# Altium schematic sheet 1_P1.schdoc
size 518 x 218 mm; Symbol: Drawing-Symbol_A4; Device: Drawing-Symbol_A4; @Project Name: LED tower pcb; @Page Count: 1; @Update Date: 2025-07-06; @Create Date: 2025-07-06; @Schematic Name: Schematic1; @Page No: 1; @Page Name: P1; Company: EasyEDA.com; Version: V1.0; Page Size: A4; @Create Time: 21:22:16; @Update Time: 17:22:16; Width: 2000; Height: 825; Region Start: 1; X Region Count: 6; Y Region Count: 4; Blade Width: 10; Title Block Position: 3; @Board Name: Board1
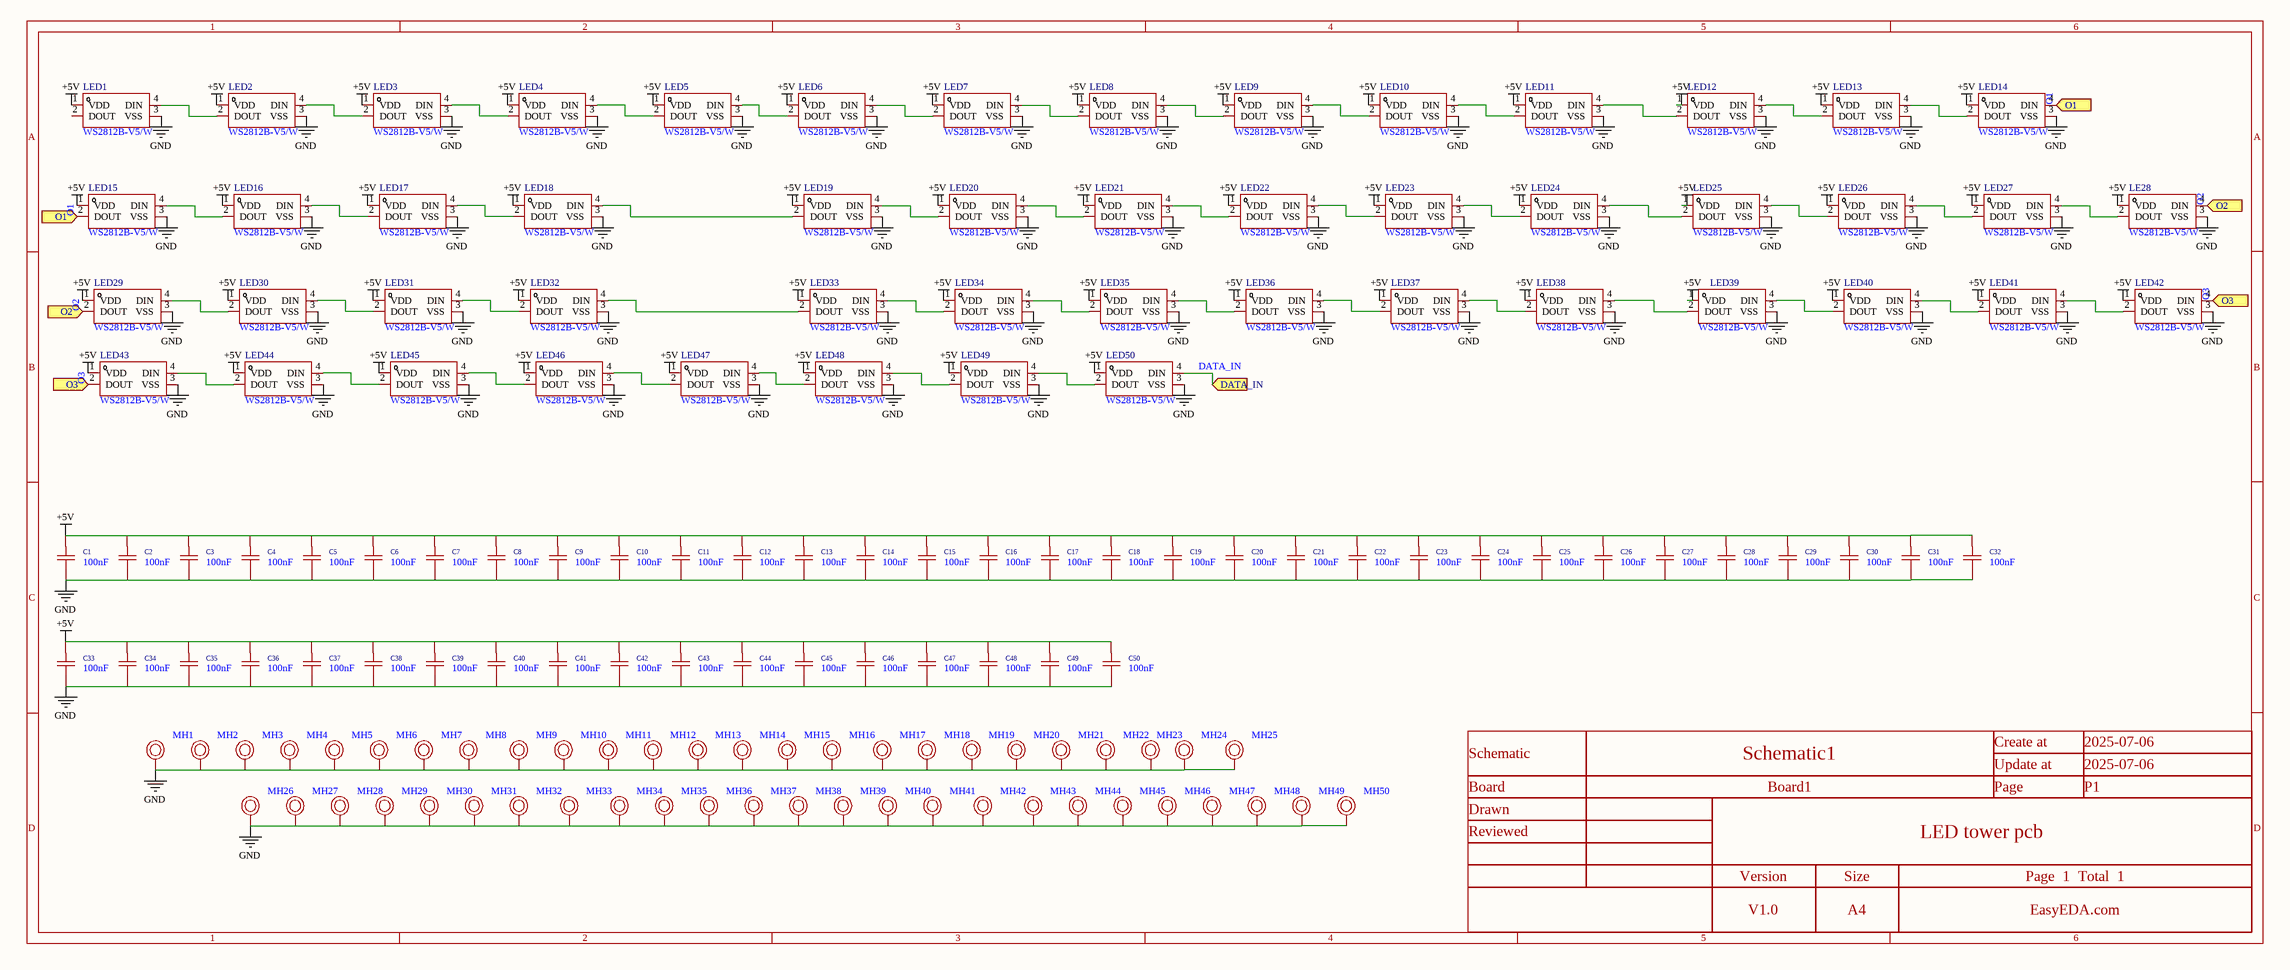
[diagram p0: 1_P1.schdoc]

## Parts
C1  100nF  [C0402]
C2  100nF  [C0402]
C3  100nF  [C0402]
C4  100nF  [C0402]
C5  100nF  [C0402]
C6  100nF  [C0402]
C7  100nF  [C0402]
C8  100nF  [C0402]
C9  100nF  [C0402]
C10  100nF  [C0402]
C11  100nF  [C0402]
C12  100nF  [C0402]
C13  100nF  [C0402]
C14  100nF  [C0402]
C15  100nF  [C0402]
C16  100nF  [C0402]
C17  100nF  [C0402]
C18  100nF  [C0402]
C19  100nF  [C0402]
C20  100nF  [C0402]
C21  100nF  [C0402]
C22  100nF  [C0402]
C23  100nF  [C0402]
C24  100nF  [C0402]
C25  100nF  [C0402]
C26  100nF  [C0402]
C27  100nF  [C0402]
C28  100nF  [C0402]
C29  100nF  [C0402]
C30  100nF  [C0402]
C31  100nF  [C0402]
C32  100nF  [C0402]
C33  100nF  [C0402]
C34  100nF  [C0402]
C35  100nF  [C0402]
C36  100nF  [C0402]
C37  100nF  [C0402]
C38  100nF  [C0402]
C39  100nF  [C0402]
C40  100nF  [C0402]
C41  100nF  [C0402]
C42  100nF  [C0402]
C43  100nF  [C0402]
C44  100nF  [C0402]
C45  100nF  [C0402]
C46  100nF  [C0402]
C47  100nF  [C0402]
C48  100nF  [C0402]
C49  100nF  [C0402]
C50  100nF  [C0402]
LE28  WS2812B-V5/W  [LED-SMD_4P-L5.0-W5.0-TL-1]
LED1  WS2812B-V5/W  [LED-SMD_4P-L5.0-W5.0-TL-1]
LED2  WS2812B-V5/W  [LED-SMD_4P-L5.0-W5.0-TL-1]
LED3  WS2812B-V5/W  [LED-SMD_4P-L5.0-W5.0-TL-1]
LED4  WS2812B-V5/W  [LED-SMD_4P-L5.0-W5.0-TL-1]
LED5  WS2812B-V5/W  [LED-SMD_4P-L5.0-W5.0-TL-1]
LED6  WS2812B-V5/W  [LED-SMD_4P-L5.0-W5.0-TL-1]
LED7  WS2812B-V5/W  [LED-SMD_4P-L5.0-W5.0-TL-1]
LED8  WS2812B-V5/W  [LED-SMD_4P-L5.0-W5.0-TL-1]
LED9  WS2812B-V5/W  [LED-SMD_4P-L5.0-W5.0-TL-1]
LED10  WS2812B-V5/W  [LED-SMD_4P-L5.0-W5.0-TL-1]
LED11  WS2812B-V5/W  [LED-SMD_4P-L5.0-W5.0-TL-1]
LED12  WS2812B-V5/W  [LED-SMD_4P-L5.0-W5.0-TL-1]
LED13  WS2812B-V5/W  [LED-SMD_4P-L5.0-W5.0-TL-1]
LED14  WS2812B-V5/W  [LED-SMD_4P-L5.0-W5.0-TL-1]
LED15  WS2812B-V5/W  [LED-SMD_4P-L5.0-W5.0-TL-1]
LED16  WS2812B-V5/W  [LED-SMD_4P-L5.0-W5.0-TL-1]
LED17  WS2812B-V5/W  [LED-SMD_4P-L5.0-W5.0-TL-1]
LED18  WS2812B-V5/W  [LED-SMD_4P-L5.0-W5.0-TL-1]
LED19  WS2812B-V5/W  [LED-SMD_4P-L5.0-W5.0-TL-1]
LED20  WS2812B-V5/W  [LED-SMD_4P-L5.0-W5.0-TL-1]
LED21  WS2812B-V5/W  [LED-SMD_4P-L5.0-W5.0-TL-1]
LED22  WS2812B-V5/W  [LED-SMD_4P-L5.0-W5.0-TL-1]
LED23  WS2812B-V5/W  [LED-SMD_4P-L5.0-W5.0-TL-1]
LED24  WS2812B-V5/W  [LED-SMD_4P-L5.0-W5.0-TL-1]
LED25  WS2812B-V5/W  [LED-SMD_4P-L5.0-W5.0-TL-1]
LED26  WS2812B-V5/W  [LED-SMD_4P-L5.0-W5.0-TL-1]
LED27  WS2812B-V5/W  [LED-SMD_4P-L5.0-W5.0-TL-1]
LED29  WS2812B-V5/W  [LED-SMD_4P-L5.0-W5.0-TL-1]
LED30  WS2812B-V5/W  [LED-SMD_4P-L5.0-W5.0-TL-1]
LED31  WS2812B-V5/W  [LED-SMD_4P-L5.0-W5.0-TL-1]
LED32  WS2812B-V5/W  [LED-SMD_4P-L5.0-W5.0-TL-1]
LED33  WS2812B-V5/W  [LED-SMD_4P-L5.0-W5.0-TL-1]
LED34  WS2812B-V5/W  [LED-SMD_4P-L5.0-W5.0-TL-1]
LED35  WS2812B-V5/W  [LED-SMD_4P-L5.0-W5.0-TL-1]
LED36  WS2812B-V5/W  [LED-SMD_4P-L5.0-W5.0-TL-1]
LED37  WS2812B-V5/W  [LED-SMD_4P-L5.0-W5.0-TL-1]
LED38  WS2812B-V5/W  [LED-SMD_4P-L5.0-W5.0-TL-1]
LED39  WS2812B-V5/W  [LED-SMD_4P-L5.0-W5.0-TL-1]
LED40  WS2812B-V5/W  [LED-SMD_4P-L5.0-W5.0-TL-1]
LED41  WS2812B-V5/W  [LED-SMD_4P-L5.0-W5.0-TL-1]
LED42  WS2812B-V5/W  [LED-SMD_4P-L5.0-W5.0-TL-1]
LED43  WS2812B-V5/W  [LED-SMD_4P-L5.0-W5.0-TL-1]
LED44  WS2812B-V5/W  [LED-SMD_4P-L5.0-W5.0-TL-1]
LED45  WS2812B-V5/W  [LED-SMD_4P-L5.0-W5.0-TL-1]
LED46  WS2812B-V5/W  [LED-SMD_4P-L5.0-W5.0-TL-1]
LED47  WS2812B-V5/W  [LED-SMD_4P-L5.0-W5.0-TL-1]
LED48  WS2812B-V5/W  [LED-SMD_4P-L5.0-W5.0-TL-1]
LED49  WS2812B-V5/W  [LED-SMD_4P-L5.0-W5.0-TL-1]
LED50  WS2812B-V5/W  [LED-SMD_4P-L5.0-W5.0-TL-1]
MH1  (no value)  [M3_Hole]
MH2  (no value)  [M3_Hole]
MH3  (no value)  [M3_Hole]
MH4  (no value)  [M3_Hole]
MH5  (no value)  [M3_Hole]
MH6  (no value)  [M3_Hole]
MH7  (no value)  [M3_Hole]
MH8  (no value)  [M3_Hole]
MH9  (no value)  [M3_Hole]
MH10  (no value)  [M3_Hole]
MH11  (no value)  [M3_Hole]
MH12  (no value)  [M3_Hole]
MH13  (no value)  [M3_Hole]
MH14  (no value)  [M3_Hole]
MH15  (no value)  [M3_Hole]
MH16  (no value)  [M3_Hole]
MH17  (no value)  [M3_Hole]
MH18  (no value)  [M3_Hole]
MH19  (no value)  [M3_Hole]
MH20  (no value)  [M3_Hole]
MH21  (no value)  [M3_Hole]
MH22  (no value)  [M3_Hole]
MH23  (no value)  [M3_Hole]
MH24  (no value)  [M3_Hole]
MH25  (no value)  [M3_Hole]
MH26  (no value)  [M3_Hole]
MH27  (no value)  [M3_Hole]
MH28  (no value)  [M3_Hole]
MH29  (no value)  [M3_Hole]
MH30  (no value)  [M3_Hole]
MH31  (no value)  [M3_Hole]
MH32  (no value)  [M3_Hole]
MH33  (no value)  [M3_Hole]
MH34  (no value)  [M3_Hole]
MH35  (no value)  [M3_Hole]
MH36  (no value)  [M3_Hole]
MH37  (no value)  [M3_Hole]
MH38  (no value)  [M3_Hole]
MH39  (no value)  [M3_Hole]
MH40  (no value)  [M3_Hole]
MH41  (no value)  [M3_Hole]
MH42  (no value)  [M3_Hole]
MH43  (no value)  [M3_Hole]
MH44  (no value)  [M3_Hole]
MH45  (no value)  [M3_Hole]
MH46  (no value)  [M3_Hole]
MH47  (no value)  [M3_Hole]
MH48  (no value)  [M3_Hole]
MH49  (no value)  [M3_Hole]
MH50  (no value)  [M3_Hole]

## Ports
DATA_IN (in), O1 (in), O2 (in), O3 (in)

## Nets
+5V: C1.2 C2.2 C3.2 C4.2 C5.2 C6.2 C7.2 C8.2 C9.2 C10.2 C11.2 C12.2 C13.2 C14.2 C15.2 C16.2 C17.2 C18.2 C19.2 C20.2 C21.2 C22.2 C23.2 C24.2 C25.2 C26.2 C27.2 C28.2 C29.2 C30.2 C31.2 C32.2 C33.2 C34.2 C35.2 C36.2 C37.2 C38.2 C39.2 C40.2 C41.2 C42.2 C43.2 C44.2 C45.2 C46.2 C47.2 C48.2 C49.2 C50.2 LE28.1(VDD) LED1.1(VDD) LED2.1(VDD) LED3.1(VDD) LED4.1(VDD) LED5.1(VDD) LED6.1(VDD) LED7.1(VDD) LED8.1(VDD) LED9.1(VDD) LED10.1(VDD) LED11.1(VDD) LED12.1(VDD) LED13.1(VDD) LED14.1(VDD) LED15.1(VDD) LED16.1(VDD) LED17.1(VDD) LED18.1(VDD) LED19.1(VDD) LED20.1(VDD) LED21.1(VDD) LED22.1(VDD) LED23.1(VDD) LED24.1(VDD) LED25.1(VDD) LED26.1(VDD) LED27.1(VDD) LED29.1(VDD) LED30.1(VDD) LED31.1(VDD) LED32.1(VDD) LED33.1(VDD) LED34.1(VDD) LED35.1(VDD) LED36.1(VDD) LED37.1(VDD) LED38.1(VDD) LED39.1(VDD) LED40.1(VDD) LED41.1(VDD) LED42.1(VDD) LED43.1(VDD) LED44.1(VDD) LED45.1(VDD) LED46.1(VDD) LED47.1(VDD) LED48.1(VDD) LED49.1(VDD) LED50.1(VDD)
GND: C1.1 C2.1 C3.1 C4.1 C5.1 C6.1 C7.1 C8.1 C9.1 C10.1 C11.1 C12.1 C13.1 C14.1 C15.1 C16.1 C17.1 C18.1 C19.1 C20.1 C21.1 C22.1 C23.1 C24.1 C25.1 C26.1 C27.1 C28.1 C29.1 C30.1 C31.1 C32.1 C33.1 C34.1 C35.1 C36.1 C37.1 C38.1 C39.1 C40.1 C41.1 C42.1 C43.1 C44.1 C45.1 C46.1 C47.1 C48.1 C49.1 C50.1 LE28.3(VSS) LED1.3(VSS) LED2.3(VSS) LED3.3(VSS) LED4.3(VSS) LED5.3(VSS) LED6.3(VSS) LED7.3(VSS) LED8.3(VSS) LED9.3(VSS) LED10.3(VSS) LED11.3(VSS) LED12.3(VSS) LED13.3(VSS) LED14.3(VSS) LED15.3(VSS) LED16.3(VSS) LED17.3(VSS) LED18.3(VSS) LED19.3(VSS) LED20.3(VSS) LED21.3(VSS) LED22.3(VSS) LED23.3(VSS) LED24.3(VSS) LED25.3(VSS) LED26.3(VSS) LED27.3(VSS) LED29.3(VSS) LED30.3(VSS) LED31.3(VSS) LED32.3(VSS) LED33.3(VSS) LED34.3(VSS) LED35.3(VSS) LED36.3(VSS) LED37.3(VSS) LED38.3(VSS) LED39.3(VSS) LED40.3(VSS) LED41.3(VSS) LED42.3(VSS) LED43.3(VSS) LED44.3(VSS) LED45.3(VSS) LED46.3(VSS) LED47.3(VSS) LED48.3(VSS) LED49.3(VSS) LED50.3(VSS) MH1.1 MH2.1 MH3.1 MH4.1 MH5.1 MH6.1 MH7.1 MH8.1 MH9.1 MH10.1 MH11.1 MH12.1 MH13.1 MH14.1 MH15.1 MH16.1 MH17.1 MH18.1 MH19.1 MH20.1 MH21.1 MH22.1 MH23.1 MH24.1 MH25.1 MH26.1 MH27.1 MH28.1 MH29.1 MH30.1 MH31.1 MH32.1 MH33.1 MH34.1 MH35.1 MH36.1 MH37.1 MH38.1 MH39.1 MH40.1 MH41.1 MH42.1 MH43.1 MH44.1 MH45.1 MH46.1 MH47.1 MH48.1 MH49.1 MH50.1
DATA_IN: LED50.4(DIN) ; port DATA_IN
O1: LED14.4(DIN) LED15.2(DOUT) ; port O1
O2: LE28.4(DIN) LED29.2(DOUT) ; port O2
O3: LED42.4(DIN) LED43.2(DOUT) ; port O3
NetLE28_2: LE28.2(DOUT) LED27.4(DIN)
NetLED1_4: LED1.4(DIN) LED2.2(DOUT)
NetLED2_4: LED2.4(DIN) LED3.2(DOUT)
NetLED3_4: LED3.4(DIN) LED4.2(DOUT)
NetLED4_4: LED4.4(DIN) LED5.2(DOUT)
NetLED5_4: LED5.4(DIN) LED6.2(DOUT)
NetLED6_4: LED6.4(DIN) LED7.2(DOUT)
NetLED7_4: LED7.4(DIN) LED8.2(DOUT)
NetLED8_4: LED8.4(DIN) LED9.2(DOUT)
NetLED9_4: LED9.4(DIN) LED10.2(DOUT)
NetLED10_4: LED10.4(DIN) LED11.2(DOUT)
NetLED11_4: LED11.4(DIN) LED12.2(DOUT)
NetLED12_4: LED12.4(DIN) LED13.2(DOUT)
NetLED13_4: LED13.4(DIN) LED14.2(DOUT)
NetLED15_4: LED15.4(DIN) LED16.2(DOUT)
NetLED16_4: LED16.4(DIN) LED17.2(DOUT)
NetLED17_4: LED17.4(DIN) LED18.2(DOUT)
NetLED18_4: LED18.4(DIN) LED19.2(DOUT)
NetLED19_4: LED19.4(DIN) LED20.2(DOUT)
NetLED20_4: LED20.4(DIN) LED21.2(DOUT)
NetLED21_4: LED21.4(DIN) LED22.2(DOUT)
NetLED22_4: LED22.4(DIN) LED23.2(DOUT)
NetLED23_4: LED23.4(DIN) LED24.2(DOUT)
NetLED24_4: LED24.4(DIN) LED25.2(DOUT)
NetLED25_4: LED25.4(DIN) LED26.2(DOUT)
NetLED26_4: LED26.4(DIN) LED27.2(DOUT)
NetLED29_4: LED29.4(DIN) LED30.2(DOUT)
NetLED30_4: LED30.4(DIN) LED31.2(DOUT)
NetLED31_4: LED31.4(DIN) LED32.2(DOUT)
NetLED32_4: LED32.4(DIN) LED33.2(DOUT)
NetLED33_4: LED33.4(DIN) LED34.2(DOUT)
NetLED34_4: LED34.4(DIN) LED35.2(DOUT)
NetLED35_4: LED35.4(DIN) LED36.2(DOUT)
NetLED36_4: LED36.4(DIN) LED37.2(DOUT)
NetLED37_4: LED37.4(DIN) LED38.2(DOUT)
NetLED38_4: LED38.4(DIN) LED39.2(DOUT)
NetLED39_4: LED39.4(DIN) LED40.2(DOUT)
NetLED40_4: LED40.4(DIN) LED41.2(DOUT)
NetLED41_4: LED41.4(DIN) LED42.2(DOUT)
NetLED43_4: LED43.4(DIN) LED44.2(DOUT)
NetLED44_4: LED44.4(DIN) LED45.2(DOUT)
NetLED45_4: LED45.4(DIN) LED46.2(DOUT)
NetLED46_4: LED46.4(DIN) LED47.2(DOUT)
NetLED47_4: LED47.4(DIN) LED48.2(DOUT)
NetLED48_4: LED48.4(DIN) LED49.2(DOUT)
NetLED49_4: LED49.4(DIN) LED50.2(DOUT)

Not connected (* = marked no-connect by the designer): LED1 2(DOUT)

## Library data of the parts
C1-C50 = CC0402KRX7R7BB104: Manufacturer: YAGEO(国巨); Add into BOM: yes; Tolerance: ±10%
LE28 LED1-LED27 LED29-LED50 = WS2812B-V5/W: Manufacturer: worldsemi; Add into BOM: yes
MH1-MH50 = M3_Hole: Add into BOM: no; Convert to PCB: yes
